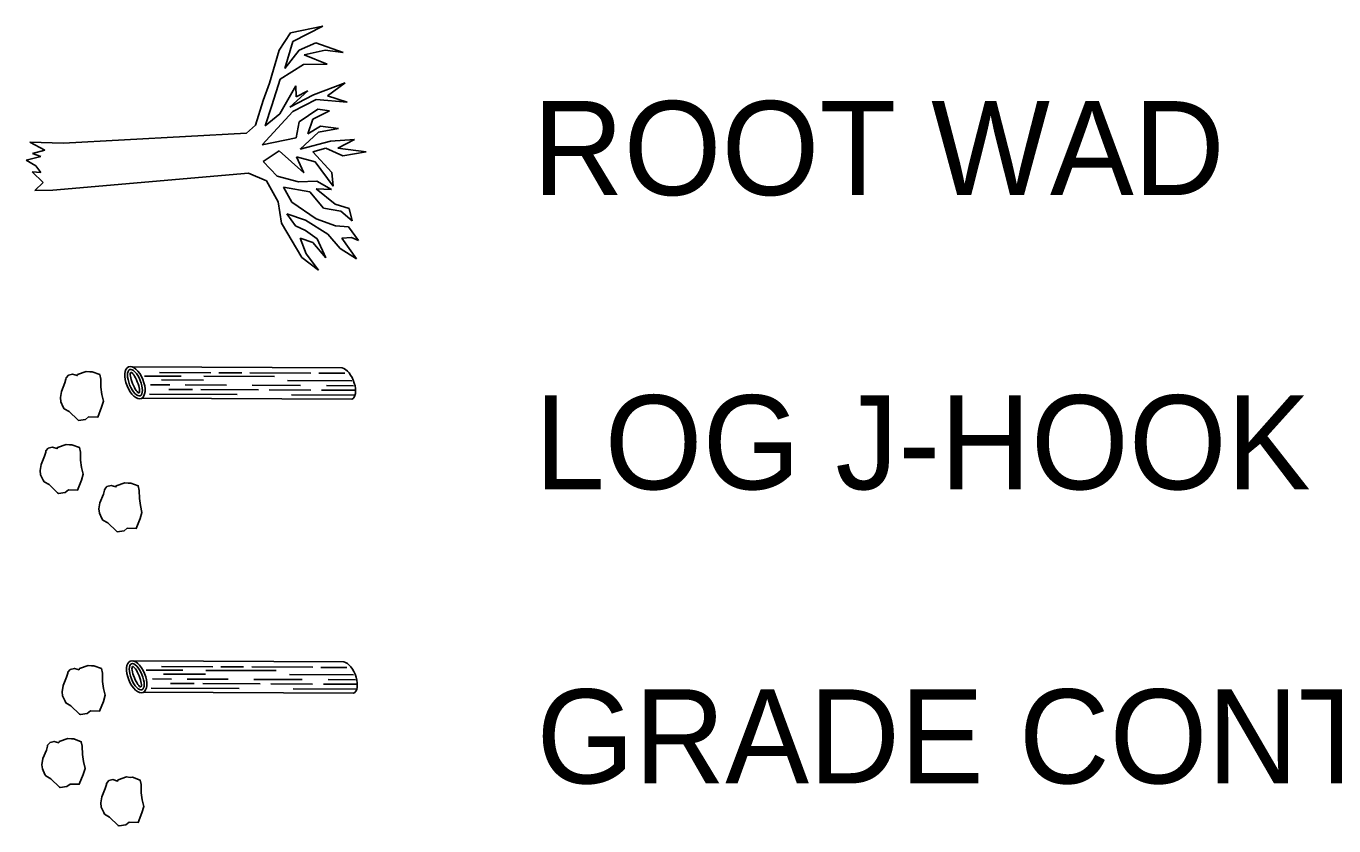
# Model space of a CAD drawing. Extents: x 1577194 to 26153757, y 723342 to 3772486.
# Drawn here: x 1577323.2 to 1577427.5, y 724396.2 to 724460 of the extents above; entities that cross this region are included whole.
import ezdxf

# ---------------------------------------------------------------- set-up
doc = ezdxf.new("R2010")
doc.units = 0
doc.layers.add('L-CL', color=7, linetype='Continuous')

msp = doc.modelspace()

# ---------------------------------------------------------------- linework, layer by layer
at = {"layer": 'L-CL'}
for p, q in [((1577346.89, 724459.97), (1577344.31, 724459.44)), ((1577344.51, 724458.74), (1577346.89, 724459.97)), ((1577343.43, 724458.05), (1577344.31, 724459.44)), ((1577343.87, 724456.6), (1577344.51, 724458.74)), ((1577346.35, 724458.63), (1577345.02, 724458.05)), ((1577348.52, 724457.86), (1577346.35, 724458.63)), ((1577343.43, 724458.05), (1577342.66, 724455.41)), ((1577345.02, 724458.05), (1577343.87, 724456.6)), ((1577345.42, 724457.68), (1577347.08, 724458.06)), ((1577347.25, 724456.93), (1577345.42, 724457.68)), ((1577347.08, 724458.06), (1577348.52, 724457.86)), ((1577343.5, 724455.73), (1577345.36, 724456.91)), ((1577345.36, 724456.91), (1577347.25, 724456.93)), ((1577342.66, 724455.41), (1577342.15, 724454.03)), ((1577342.82, 724453.65), (1577343.5, 724455.73)), ((1577348.67, 724455.44), (1577346.15, 724454.49)), ((1577347.26, 724454.4), (1577348.67, 724455.44)), ((1577344.75, 724455.2), (1577343.46, 724452.99)), ((1577344.27, 724453.52), (1577345.7, 724454.82)), ((1577346.15, 724454.49), (1577344.27, 724453.52)), ((1577344.77, 724454.34), (1577344.75, 724455.2)), ((1577345.7, 724454.82), (1577344.77, 724454.34)), ((1577348.85, 724453.92), (1577347.26, 724454.4)), ((1577342.15, 724454.03), (1577341.54, 724452.07)), ((1577342.3, 724452.01), (1577342.82, 724453.65)), ((1577344.5, 724453.16), (1577346.38, 724454.12)), ((1577346.5, 724453.36), (1577345.01, 724452.33)), ((1577346.11, 724452.56), (1577347.44, 724453.22)), ((1577346.38, 724454.12), (1577348.85, 724453.92)), ((1577347.44, 724453.22), (1577346.5, 724453.36)), ((1577342.06, 724450.52), (1577344.5, 724453.16)), ((1577343.46, 724452.99), (1577342.3, 724452.01)), ((1577345.01, 724452.33), (1577344.78, 724451.07)), ((1577345.7, 724451.38), (1577346.11, 724452.56)), ((1577340.8, 724451.44), (1577326.23, 724450.64)), ((1577341.54, 724452.07), (1577340.8, 724451.44)), ((1577345.09, 724450.15), (1577346.54, 724451.51)), ((1577346.71, 724452), (1577345.7, 724451.38)), ((1577346.54, 724451.51), (1577348.16, 724451.82)), ((1577348.16, 724451.82), (1577346.71, 724452)), ((1577324.73, 724450.08), (1577323.53, 724450.73)), ((1577323.53, 724450.73), (1577326.23, 724450.64)), ((1577323.76, 724449.81), (1577324.73, 724450.08)), ((1577344.78, 724451.07), (1577342.06, 724450.52)), ((1577347.5, 724450.79), (1577345.09, 724450.15)), ((1577346.1, 724449.94), (1577347.14, 724450.24)), ((1577347.14, 724450.24), (1577348.5, 724449.62)), ((1577349.43, 724450.92), (1577347.5, 724450.79)), ((1577348.1, 724450.23), (1577349.43, 724450.92)), ((1577350.34, 724449.94), (1577348.1, 724450.23)), ((1577323.25, 724449.29), (1577324.43, 724449.58)), ((1577324.03, 724448.84), (1577323.25, 724449.29)), ((1577324.43, 724449.58), (1577323.76, 724449.81)), ((1577342.14, 724449.18), (1577343.43, 724450.03)), ((1577343.26, 724448), (1577342.14, 724449.18)), ((1577343.43, 724450.03), (1577345.39, 724448.28)), ((1577345.39, 724448.28), (1577344.79, 724449.54)), ((1577344.79, 724449.54), (1577346.29, 724449.16)), ((1577347.62, 724448.29), (1577346.1, 724449.94)), ((1577346.29, 724449.16), (1577347.73, 724447.2)), ((1577348.5, 724449.62), (1577350.34, 724449.94)), ((1577324.61, 724447.51), (1577323.73, 724448.35)), ((1577323.73, 724448.35), (1577324.41, 724448.3)), ((1577324.41, 724448.3), (1577324.03, 724448.84)), ((1577325.37, 724446.89), (1577340.97, 724448.25)), ((1577340.97, 724448.25), (1577342.4, 724447.63)), ((1577344.95, 724447.55), (1577343.26, 724448)), ((1577347.73, 724447.2), (1577347.62, 724448.29)), ((1577323.95, 724446.87), (1577324.61, 724447.51)), ((1577342.4, 724447.63), (1577343.35, 724445.96)), ((1577344.44, 724445.93), (1577343.76, 724447.13)), ((1577343.76, 724447.13), (1577345.85, 724446.77)), ((1577346.42, 724447.62), (1577344.95, 724447.55)), ((1577347.87, 724445.78), (1577346.37, 724446.99)), ((1577346.37, 724446.99), (1577347.58, 724446.95)), ((1577347.58, 724446.95), (1577346.42, 724447.62)), ((1577325.37, 724446.89), (1577323.95, 724446.87)), ((1577343.35, 724445.96), (1577343.6, 724444.27)), ((1577346.37, 724444.62), (1577344.44, 724445.93)), ((1577345.85, 724446.77), (1577346.95, 724445.47)), ((1577344.73, 724444.06), (1577344.04, 724445)), ((1577344.04, 724445), (1577345.53, 724444.5)), ((1577346.95, 724445.47), (1577348.34, 724445.23)), ((1577348.99, 724445.43), (1577347.87, 724445.78)), ((1577348.34, 724445.23), (1577349.23, 724444.46)), ((1577349.23, 724444.46), (1577348.99, 724445.43)), ((1577343.6, 724444.27), (1577345.23, 724441.53)), ((1577345.53, 724443.67), (1577344.73, 724444.06)), ((1577345.53, 724444.5), (1577347.3, 724443.4)), ((1577347.92, 724444.05), (1577346.37, 724444.62)), ((1577348.94, 724443.97), (1577347.92, 724444.05)), ((1577349.75, 724442.89), (1577348.94, 724443.97)), ((1577345.57, 724441.82), (1577345.1, 724443.07)), ((1577345.1, 724443.07), (1577346.1, 724442.73)), ((1577346.44, 724443.02), (1577345.53, 724443.67)), ((1577347.15, 724441.5), (1577346.44, 724443.02)), ((1577347.3, 724443.4), (1577348.29, 724442.24)), ((1577348.42, 724443.06), (1577349.19, 724443.12)), ((1577349.57, 724441.43), (1577348.42, 724443.06)), ((1577349.19, 724443.12), (1577349.75, 724442.89)), ((1577346.55, 724440.53), (1577345.57, 724441.82)), ((1577346.1, 724442.73), (1577347.15, 724441.5)), ((1577348.29, 724442.24), (1577349.57, 724441.43)), ((1577345.23, 724441.53), (1577346.55, 724440.53)), ((1577348.43, 724432.74), (1577331.66, 724432.81)), ((1577337.98, 724432.34), (1577333.89, 724432.36)), ((1577335.6, 724432.07), (1577332.67, 724432.08)), ((1577334.7, 724431.37), (1577333.17, 724431.38)), ((1577337.39, 724431.75), (1577334.04, 724431.77)), ((1577339.21, 724431.35), (1577335.93, 724431.37)), ((1577343.05, 724432.04), (1577337.41, 724432.06)), ((1577340.44, 724432.33), (1577338.62, 724432.34)), ((1577345.95, 724432.31), (1577341.09, 724432.33)), ((1577345.11, 724431.33), (1577341.26, 724431.35)), ((1577349.2, 724431.7), (1577344.09, 724431.72)), ((1577348.66, 724432.3), (1577346.58, 724432.31)), ((1577349.34, 724431.31), (1577347.18, 724431.32)), ((1577349.2, 724430.24), (1577332.43, 724430.31)), ((1577340.08, 724430.6), (1577333.07, 724430.63)), ((1577336.51, 724431), (1577334.61, 724431.01)), ((1577341.76, 724430.98), (1577337.18, 724431)), ((1577345.93, 724430.96), (1577342.61, 724430.98)), ((1577349.42, 724430.56), (1577344.39, 724430.58)), ((1577349.45, 724430.95), (1577346.8, 724430.96)), ((1577327.36, 724428.58), (1577327.43, 724428.54)), ((1577325.75, 724422.76), (1577325.82, 724422.72)), ((1577330.44, 724419.71), (1577330.51, 724419.67)), ((1577348.58, 724409.3), (1577331.8, 724409.37)), ((1577335.74, 724408.63), (1577332.82, 724408.64)), ((1577338.12, 724408.9), (1577334.04, 724408.92)), ((1577343.19, 724408.6), (1577337.56, 724408.62)), ((1577340.58, 724408.89), (1577338.77, 724408.9)), ((1577346.1, 724408.87), (1577341.23, 724408.89)), ((1577348.8, 724408.85), (1577346.73, 724408.86)), ((1577334.84, 724407.93), (1577333.31, 724407.94)), ((1577337.54, 724408.31), (1577334.19, 724408.32)), ((1577336.65, 724407.56), (1577334.75, 724407.57)), ((1577339.35, 724407.91), (1577336.08, 724407.93)), ((1577341.9, 724407.54), (1577337.32, 724407.56)), ((1577345.25, 724407.89), (1577341.4, 724407.9)), ((1577346.07, 724407.52), (1577342.76, 724407.54)), ((1577349.34, 724408.26), (1577344.24, 724408.28)), ((1577349.59, 724407.51), (1577346.94, 724407.52)), ((1577349.49, 724407.87), (1577347.32, 724407.88)), ((1577349.35, 724406.8), (1577332.57, 724406.87)), ((1577340.22, 724407.16), (1577333.21, 724407.19)), ((1577349.56, 724407.12), (1577344.53, 724407.14)), ((1577327.51, 724405.13), (1577327.57, 724405.1)), ((1577325.9, 724399.31), (1577325.96, 724399.28)), ((1577330.58, 724396.26), (1577330.65, 724396.23))]:
    msp.add_line(p, q, dxfattribs=at)
for points in [[(1577327.43, 724428.54), (1577327.97, 724428.62), (1577328.23, 724428.83), (1577328.95, 724428.8), (1577329.26, 724429.59), (1577329.4, 724430.07), (1577329.27, 724430.62), (1577329.2, 724431.18), (1577329.19, 724431.83), (1577329.11, 724432.2), (1577328.51, 724432.41), (1577328.32, 724432.41), (1577328.04, 724432.44), (1577327.35, 724432.2), (1577327.32, 724432.11), (1577326.95, 724432.22), (1577326.62, 724432.14), (1577326.43, 724431.93), (1577326.42, 724431.84), (1577326.33, 724431.53), (1577326.06, 724430.85), (1577325.98, 724430.36), (1577326.01, 724430.03), (1577326.21, 724429.6), (1577326.28, 724429.47), (1577326.68, 724429.25), (1577327.36, 724428.58)], [(1577325.82, 724422.72), (1577326.36, 724422.8), (1577326.62, 724423.01), (1577327.34, 724422.98), (1577327.65, 724423.77), (1577327.79, 724424.25), (1577327.66, 724424.8), (1577327.59, 724425.36), (1577327.58, 724426.01), (1577327.5, 724426.38), (1577326.9, 724426.59), (1577326.71, 724426.59), (1577326.43, 724426.62), (1577325.74, 724426.38), (1577325.71, 724426.29), (1577325.33, 724426.4), (1577325.01, 724426.32), (1577324.82, 724426.11), (1577324.81, 724426.02), (1577324.72, 724425.7), (1577324.44, 724425.03), (1577324.37, 724424.54), (1577324.4, 724424.21), (1577324.6, 724423.78), (1577324.67, 724423.65), (1577325.07, 724423.43), (1577325.75, 724422.76)], [(1577330.51, 724419.67), (1577331.05, 724419.75), (1577331.3, 724419.96), (1577332.03, 724419.93), (1577332.33, 724420.72), (1577332.48, 724421.2), (1577332.35, 724421.75), (1577332.28, 724422.31), (1577332.26, 724422.96), (1577332.18, 724423.33), (1577331.59, 724423.54), (1577331.39, 724423.54), (1577331.11, 724423.57), (1577330.43, 724423.33), (1577330.4, 724423.24), (1577330.02, 724423.35), (1577329.69, 724423.27), (1577329.51, 724423.05), (1577329.5, 724422.97), (1577329.41, 724422.66), (1577329.13, 724421.98), (1577329.05, 724421.49), (1577329.09, 724421.16), (1577329.28, 724420.73), (1577329.36, 724420.6), (1577329.76, 724420.38), (1577330.44, 724419.71)], [(1577327.57, 724405.1), (1577328.11, 724405.18), (1577328.37, 724405.38), (1577329.09, 724405.36), (1577329.4, 724406.15), (1577329.55, 724406.63), (1577329.42, 724407.17), (1577329.34, 724407.74), (1577329.33, 724408.39), (1577329.25, 724408.76), (1577328.65, 724408.97), (1577328.46, 724408.97), (1577328.18, 724409), (1577327.49, 724408.76), (1577327.47, 724408.67), (1577327.09, 724408.78), (1577326.76, 724408.7), (1577326.57, 724408.48), (1577326.57, 724408.4), (1577326.47, 724408.08), (1577326.2, 724407.41), (1577326.12, 724406.92), (1577326.15, 724406.59), (1577326.35, 724406.16), (1577326.42, 724406.03), (1577326.82, 724405.8), (1577327.51, 724405.13)], [(1577325.96, 724399.28), (1577326.5, 724399.36), (1577326.76, 724399.56), (1577327.48, 724399.54), (1577327.79, 724400.32), (1577327.94, 724400.81), (1577327.81, 724401.35), (1577327.73, 724401.92), (1577327.72, 724402.57), (1577327.64, 724402.93), (1577327.04, 724403.15), (1577326.85, 724403.15), (1577326.57, 724403.18), (1577325.88, 724402.94), (1577325.85, 724402.85), (1577325.48, 724402.96), (1577325.15, 724402.88), (1577324.96, 724402.66), (1577324.95, 724402.58), (1577324.86, 724402.26), (1577324.59, 724401.59), (1577324.51, 724401.1), (1577324.54, 724400.77), (1577324.74, 724400.33), (1577324.81, 724400.21), (1577325.21, 724399.98), (1577325.9, 724399.31)], [(1577330.65, 724396.23), (1577331.19, 724396.31), (1577331.45, 724396.51), (1577332.17, 724396.49), (1577332.48, 724397.27), (1577332.62, 724397.76), (1577332.49, 724398.3), (1577332.42, 724398.87), (1577332.41, 724399.52), (1577332.33, 724399.88), (1577331.73, 724400.1), (1577331.53, 724400.09), (1577331.26, 724400.13), (1577330.57, 724399.89), (1577330.54, 724399.8), (1577330.17, 724399.91), (1577329.84, 724399.83), (1577329.65, 724399.61), (1577329.64, 724399.53), (1577329.55, 724399.21), (1577329.27, 724398.54), (1577329.2, 724398.05), (1577329.23, 724397.72), (1577329.43, 724397.28), (1577329.5, 724397.16), (1577329.9, 724396.93), (1577330.58, 724396.26)]]:
    msp.add_lwpolyline(points, dxfattribs=at)
for centre, major_axis, ratio in [((1577331.92, 724431.55), (0.51, -1.25), 0.502379), ((1577331.92, 724431.55), (0.42, -1.04), 0.405893), ((1577331.92, 724431.55), (0.327, -0.806), 0.230513), ((1577332.06, 724408.11), (0.51, -1.25), 0.502379), ((1577332.06, 724408.11), (0.42, -1.04), 0.405893), ((1577332.06, 724408.11), (0.327, -0.806), 0.230513)]:
    msp.add_ellipse(centre, major_axis=major_axis, ratio=ratio, dxfattribs=at)
for centre in [(1577348.7, 724431.48), (1577348.84, 724408.04)]:
    msp.add_ellipse(centre, major_axis=(0.51, -1.25), ratio=0.502379, start_param=6.283127, end_param=9.078817, dxfattribs=at)

# ---------------------------------------------------------------- texts
for s, p in [('ROOT WAD', (1577363.64, 724446.5)), ('LOG J-HOOK', (1577363.79, 724423.05)), ('GRADE CONTROL LOG J-HOOK', (1577363.93, 724399.61))]:
    msp.add_text(s, height=7.5, dxfattribs=at).set_placement(p)

doc.saveas('drawing.dxf')
